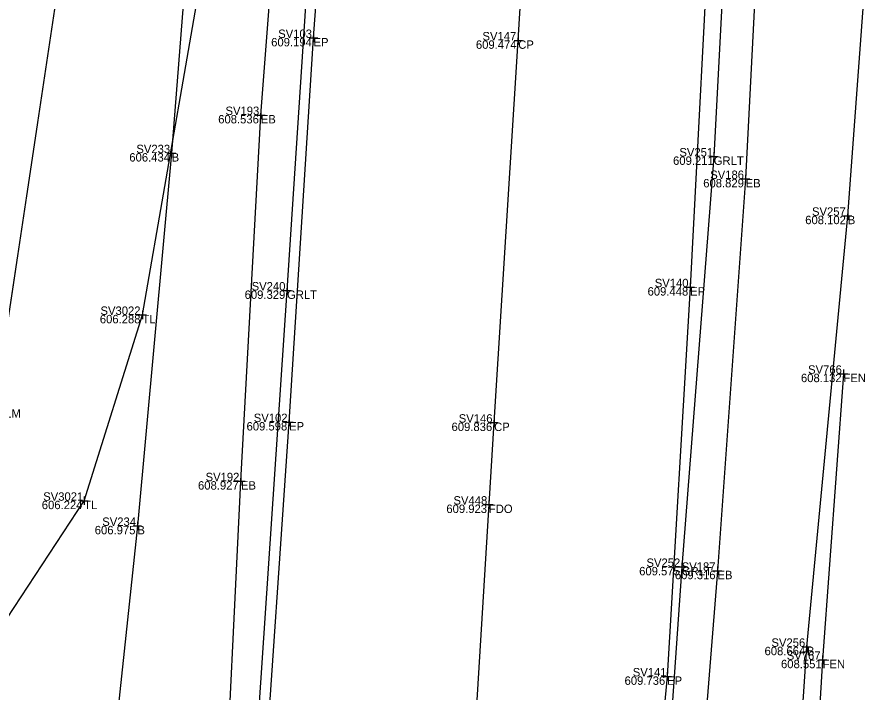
# Model space of a CAD drawing. Extents: x -2 to 1979875, y -2 to 232027.
# Drawn here: x 1978751.3 to 1978801.8, y 231321.8 to 231361.9 of the extents above; entities that cross this region are included whole.
import ezdxf

# ---------------------------------------------------------------- set-up
doc = ezdxf.new("R2010")
doc.units = 0
for name, color, linetype in [('_CIVIL_CONSTRUCTION', 7, 'Continuous'), ('GE_P_Alignment', 7, 'Continuous'), ('GE_P_Alignment_1000_Curve_Data', 7, 'Continuous'), ('GE_P_Alignment_100_Curve_Data', 7, 'Continuous'), ('GE_P_Alignment_500_Curve_Data', 7, 'Continuous'), ('GE_X_Alignment', 7, 'Continuous'), ('GE_X_Alignment_1000_Curve_Data', 7, 'Continuous'), ('GE_X_Alignment_1000_Stations', 7, 'Continuous'), ('GE_X_Alignment_100_Curve_Data', 7, 'Continuous'), ('GE_X_Alignment_100_Stations', 7, 'Continuous'), ('RD_X_Fence', 7, 'Continuous'), ('SC_Scratch1', 7, 'Continuous'), ('UT_X_Water', 7, 'Continuous')]:
    doc.layers.add(name, color=color, linetype=linetype)

msp = doc.modelspace()

# ---------------------------------------------------------------- linework, layer by layer
at = {"layer": 'GE_P_Alignment'}
for points in [[(1978861.689, 231782.415), (1978851.853, 231763.969), (1978841.987, 231745.294), (1978832.802, 231726.204), (1978823.63, 231707.125), (1978815.734, 231686.751), (1978809.08, 231664.461), (1978799.472, 231640.53), (1978791.914, 231616.771), (1978786.956, 231593.117), (1978782.497, 231568.131), (1978778.452, 231542.695), (1978775.331, 231517.531), (1978773.11, 231494.147), (1978771.443, 231473.021), (1978766.839, 231446.726), (1978765.415, 231421.944), (1978763.995, 231399.725), (1978762.317, 231376.717), (1978760.52, 231353.776), (1978758.484, 231331.627), (1978756.746, 231315.247), (1978755.236, 231305.004), (1978757.214, 231296.936)], [(1978796.543, 231298.857), (1978798.274, 231324.443), (1978800.704, 231350.055), (1978802.691, 231376.873), (1978804.911, 231401.653), (1978806.885, 231425.398), (1978807.692, 231450.453), (1978809.926, 231474.524), (1978811.781, 231491.704), (1978814.624, 231521.225), (1978818.445, 231546.214), (1978822.849, 231572.066), (1978827.059, 231594.68), (1978834.582, 231618.811), (1978841.486, 231643.192), (1978848.448, 231666.52), (1978859.661, 231691.186), (1978869.566, 231712.589), (1978880.404, 231735.407), (1978890.398, 231756.483), (1978895.241, 231765.92)]]:
    msp.add_lwpolyline(points, dxfattribs=at)
at = {"layer": 'GE_P_Alignment_1000_Curve_Data'}
msp.add_lwpolyline([(1978733.125, 231254.651), (1978737.318, 231281.706), (1978740.694, 231296.926), (1978742.413, 231306.837), (1978748.228, 231322.336), (1978755.317, 231333.122), (1978758.78, 231344.165), (1978763.011, 231368.433), (1978764.4, 231379.716), (1978765.858, 231395.082), (1978767.238, 231417.341), (1978767.097, 231431.457), (1978767.532, 231441.077), (1978768.449, 231451.786), (1978770.871, 231461.5), (1978774.002, 231474.92), (1978775.889, 231489.026), (1978776.895, 231504.336), (1978777.94, 231514.653)], dxfattribs=at)
at = {"layer": 'GE_P_Alignment_100_Curve_Data'}
for points in [[(1978764.438, 231298.773), (1978765.712, 231320.829), (1978767.378, 231345.616), (1978768.807, 231367.39), (1978770.554, 231391.673), (1978771.722, 231416.416), (1978771.842, 231435.288), (1978771.576, 231449.202)], [(1978801.365, 231447.686), (1978797.734, 231425.84), (1978795.609, 231402.949), (1978794.056, 231378.448), (1978792.74, 231353.579), (1978790.842, 231329.19), (1978789.312, 231307.337), (1978788.697, 231297.789)]]:
    msp.add_lwpolyline(points, dxfattribs=at)
at = {"layer": 'GE_P_Alignment_500_Curve_Data'}
for p, q in [((1978779.373, 231333.143), (1978779.373, 231332.643)), ((1978779.123, 231332.893), (1978779.623, 231332.893)), ((1978779.373, 231332.893), (1978779.373, 231332.893))]:
    msp.add_line(p, q, dxfattribs=at)
at = {"layer": 'GE_X_Alignment_1000_Curve_Data'}
msp.add_lwpolyline([(1978776.88, 231293.019), (1978778.313, 231315.451), (1978779.686, 231337.763), (1978781.119, 231360.475), (1978782.569, 231384.073), (1978784.079, 231408.548), (1978785.737, 231433.04), (1978787.352, 231456.369), (1978789.204, 231480.117), (1978791.477, 231503.648), (1978794.349, 231526.784), (1978797.796, 231550.891), (1978801.515, 231572.898), (1978806.442, 231596.208), (1978812.098, 231619.057), (1978818.629, 231640.775), (1978826, 231662.112), (1978835.057, 231685.412), (1978844.843, 231707.874), (1978854.489, 231728.841), (1978864.575, 231749.812), (1978877.222, 231774.568)], dxfattribs=at)
at = {"layer": 'GE_X_Alignment_1000_Stations'}
for points in [[(1978764.463, 231293.7), (1978765.973, 231315.536), (1978767.501, 231337.797), (1978768.95, 231360.619), (1978770.673, 231383.826), (1978772.372, 231407.034), (1978773.964, 231429.759), (1978775.312, 231448.487), (1978777.194, 231472.049), (1978779.086, 231494.381), (1978781.387, 231516.708), (1978784.451, 231540.773), (1978787.814, 231562.2), (1978793.416, 231590.474), (1978799.132, 231614.141), (1978805.307, 231636.271), (1978811.99, 231656.714), (1978821.006, 231681.034), (1978832.082, 231707.98), (1978843.434, 231732.641), (1978854.786, 231756.844), (1978866.633, 231780.181)], [(1978887.054, 231769.497), (1978875.688, 231747.111), (1978865.322, 231725.635), (1978856.257, 231705.079), (1978847.493, 231684.376), (1978839.463, 231663.377), (1978831.793, 231640.155), (1978824.647, 231616.117), (1978817.773, 231591.521), (1978812.873, 231567.295), (1978809.011, 231544.227), (1978805.416, 231519.882), (1978802.367, 231496.191), (1978799.68, 231465.625), (1978797.956, 231442.353), (1978795.891, 231416.691), (1978793.937, 231391.428), (1978792.627, 231370.424), (1978791.336, 231345.811), (1978789.97, 231322.684), (1978787.965, 231301.579), (1978787.711, 231292.48)]]:
    msp.add_lwpolyline(points, dxfattribs=at)
at = {"layer": 'GE_X_Alignment_100_Curve_Data'}
for p, q in [((1978768.95, 231360.869), (1978768.95, 231360.369)), ((1978781.119, 231360.725), (1978781.119, 231360.225)), ((1978768.7, 231360.619), (1978769.2, 231360.619)), ((1978768.95, 231360.619), (1978768.95, 231360.619)), ((1978780.869, 231360.475), (1978781.369, 231360.475)), ((1978781.119, 231360.475), (1978781.119, 231360.475)), ((1978765.818, 231356.292), (1978765.818, 231355.792)), ((1978765.568, 231356.042), (1978766.068, 231356.042)), ((1978765.818, 231356.042), (1978765.818, 231356.042)), ((1978760.27, 231353.776), (1978760.77, 231353.776)), ((1978760.52, 231354.026), (1978760.52, 231353.526)), ((1978760.52, 231353.776), (1978760.52, 231353.776)), ((1978792.74, 231353.829), (1978792.74, 231353.329)), ((1978792.49, 231353.579), (1978792.99, 231353.579)), ((1978792.74, 231353.579), (1978792.74, 231353.579)), ((1978794.385, 231352.241), (1978794.885, 231352.241)), ((1978794.635, 231352.491), (1978794.635, 231351.991)), ((1978794.635, 231352.241), (1978794.635, 231352.241)), ((1978800.704, 231350.305), (1978800.704, 231349.805)), ((1978800.454, 231350.055), (1978800.954, 231350.055)), ((1978800.704, 231350.055), (1978800.704, 231350.055)), ((1978767.128, 231345.616), (1978767.628, 231345.616)), ((1978767.378, 231345.866), (1978767.378, 231345.366)), ((1978767.378, 231345.616), (1978767.378, 231345.616)), ((1978791.086, 231345.811), (1978791.586, 231345.811)), ((1978791.336, 231346.061), (1978791.336, 231345.561)), ((1978791.336, 231345.811), (1978791.336, 231345.811)), ((1978758.53, 231344.165), (1978759.03, 231344.165)), ((1978758.78, 231344.415), (1978758.78, 231343.915)), ((1978758.78, 231344.165), (1978758.78, 231344.165)), ((1978800.2, 231340.668), (1978800.7, 231340.668)), ((1978800.45, 231340.918), (1978800.45, 231340.418)), ((1978800.45, 231340.668), (1978800.45, 231340.668)), ((1978767.501, 231338.047), (1978767.501, 231337.547)), ((1978779.686, 231338.013), (1978779.686, 231337.513)), ((1978767.251, 231337.797), (1978767.751, 231337.797)), ((1978767.501, 231337.797), (1978767.501, 231337.797)), ((1978779.436, 231337.763), (1978779.936, 231337.763)), ((1978779.686, 231337.763), (1978779.686, 231337.763)), ((1978764.638, 231334.533), (1978764.638, 231334.033)), ((1978764.388, 231334.283), (1978764.888, 231334.283)), ((1978764.638, 231334.283), (1978764.638, 231334.283)), ((1978755.067, 231333.122), (1978755.567, 231333.122)), ((1978755.317, 231333.372), (1978755.317, 231332.872)), ((1978755.317, 231333.122), (1978755.317, 231333.122)), ((1978758.234, 231331.627), (1978758.734, 231331.627)), ((1978758.484, 231331.877), (1978758.484, 231331.377)), ((1978758.484, 231331.627), (1978758.484, 231331.627)), ((1978790.842, 231329.44), (1978790.842, 231328.94)), ((1978790.592, 231329.19), (1978791.092, 231329.19)), ((1978790.842, 231329.19), (1978790.842, 231329.19)), ((1978792.711, 231328.96), (1978793.211, 231328.96)), ((1978792.961, 231329.21), (1978792.961, 231328.71)), ((1978792.961, 231328.96), (1978792.961, 231328.96)), ((1978798.024, 231324.443), (1978798.524, 231324.443)), ((1978798.274, 231324.693), (1978798.274, 231324.193)), ((1978798.274, 231324.443), (1978798.274, 231324.443)), ((1978799.207, 231323.921), (1978799.207, 231323.421)), ((1978798.957, 231323.671), (1978799.457, 231323.671)), ((1978799.207, 231323.671), (1978799.207, 231323.671)), ((1978789.97, 231322.934), (1978789.97, 231322.434)), ((1978789.72, 231322.684), (1978790.22, 231322.684)), ((1978789.97, 231322.684), (1978789.97, 231322.684))]:
    msp.add_line(p, q, dxfattribs=at)
at = {"layer": 'RD_X_Fence'}
msp.add_lwpolyline([(1978800.45, 231340.668), (1978799.207, 231323.671), (1978798.282, 231308.486), (1978798.968, 231301.846)], dxfattribs=at)
at = {"layer": 'SC_Scratch1'}
for points in [[(1978762.241, 231295.643), (1978763.575, 231312.653), (1978764.638, 231334.283), (1978765.818, 231356.042), (1978767.705, 231380.515), (1978769.009, 231402.257), (1978769.844, 231423.935), (1978772.522, 231443.246), (1978774.792, 231466.077), (1978776.974, 231489.898), (1978779.234, 231514.617), (1978782.489, 231539.582), (1978786.101, 231563.808), (1978790.249, 231586.35), (1978795.964, 231611.211), (1978802.838, 231634.974), (1978810.373, 231657.227), (1978818.1, 231678.589), (1978826.474, 231699.286), (1978835.162, 231719.41), (1978844.319, 231739.683), (1978854.914, 231761.571), (1978865.037, 231781.151)], [(1978888.808, 231768.485), (1978877.882, 231747.21), (1978866.825, 231724.389), (1978857.223, 231702.339), (1978848.244, 231681.507), (1978839.526, 231658.205), (1978831.772, 231633.737), (1978825.103, 231611.479), (1978819.562, 231589.918), (1978815.237, 231567.914), (1978810.741, 231543.659), (1978807.235, 231520.012), (1978805.099, 231498.598), (1978802.191, 231475.113), (1978800.521, 231451.185), (1978799.203, 231426.897), (1978797.071, 231402.161), (1978795.912, 231377.319), (1978794.635, 231352.241), (1978792.961, 231328.96), (1978791.062, 231305.225), (1978790.036, 231294.396)]]:
    msp.add_lwpolyline(points, dxfattribs=at)
at = {"layer": 'UT_X_Water'}
msp.add_lwpolyline([(1978712.49, 231209.97), (1978714.812, 231240.893), (1978716.641, 231256.079), (1978724.417, 231285.176), (1978739.059, 231319.254), (1978749.995, 231338.561), (1978758.981, 231398.401), (1978764.286, 231459.71)], dxfattribs=at)

# ---------------------------------------------------------------- texts
at = {"layer": '_CIVIL_CONSTRUCTION'}
for s, p in [('609.194', (1978766.434, 231360.119)), ('609.474', (1978778.603, 231359.975)), ('608.536', (1978763.286, 231355.542)), ('606.434', (1978758.004, 231353.276)), ('609.211', (1978790.322, 231353.079)), ('608.829', (1978792.114, 231351.741)), ('608.102', (1978798.176, 231349.555)), ('609.329', (1978764.857, 231345.116)), ('609.448', (1978788.806, 231345.311)), ('606.288', (1978756.25, 231343.665)), ('608.132', (1978797.922, 231340.168)), ('609.598', (1978764.971, 231337.297)), ('609.836', (1978777.154, 231337.263)), ('608.927', (1978762.087, 231333.783)), ('606.224', (1978752.801, 231332.622)), ('609.923', (1978776.848, 231332.393)), ('606.975', (1978755.949, 231331.127)), ('609.575', (1978788.307, 231328.69)), ('609.316', (1978790.429, 231328.46)), ('608.664', (1978795.758, 231323.943)), ('608.551', (1978796.737, 231323.171)), ('609.736', (1978787.438, 231322.184))]:
    msp.add_text(s, height=0.5, dxfattribs=at).set_placement(p)
at = {"layer": 'GE_X_Alignment'}
for s, p in [('SV103', (1978766.852, 231360.619)), ('SV147', (1978778.994, 231360.475)), ('SV193', (1978763.72, 231356.042)), ('SV233', (1978758.422, 231353.776)), ('SV251', (1978790.697, 231353.579)), ('SV186', (1978792.53, 231352.241)), ('SV257', (1978798.579, 231350.055)), ('SV240', (1978765.274, 231345.616)), ('SV140', (1978789.232, 231345.811)), ('SV3022', (1978756.29, 231344.165)), ('SV766', (1978798.345, 231340.668)), ('SV102', (1978765.4, 231337.797)), ('SV146', (1978777.581, 231337.763)), ('SV192', (1978762.537, 231334.283)), ('SV3021', (1978752.885, 231333.122)), ('SV448', (1978777.27, 231332.893)), ('SV234', (1978756.395, 231331.627)), ('SV252', (1978788.741, 231329.19)), ('SV187', (1978790.836, 231328.96)), ('SV256', (1978796.169, 231324.443)), ('SV767', (1978797.082, 231323.671)), ('SV141', (1978787.927, 231322.684))]:
    msp.add_text(s, height=0.5, dxfattribs=at).set_placement(p)
at = {"layer": 'GE_X_Alignment_100_Stations'}
for s, p in [('EP', (1978768.95, 231360.119)), ('CP', (1978781.119, 231359.975)), ('EB', (1978765.818, 231355.542)), ('B', (1978760.52, 231353.276)), ('GRLT', (1978792.74, 231353.079)), ('EB', (1978794.635, 231351.741)), ('B', (1978800.704, 231349.555)), ('GRLT', (1978767.378, 231345.116)), ('EP', (1978791.336, 231345.311)), ('TL', (1978758.78, 231343.665)), ('FEN', (1978800.45, 231340.168)), ('WLM', (1978749.995, 231338.061)), ('EP', (1978767.501, 231337.297)), ('CP', (1978779.686, 231337.263)), ('EB', (1978764.638, 231333.783)), ('TL', (1978755.317, 231332.622)), ('FDO', (1978779.373, 231332.393)), ('B', (1978758.484, 231331.127)), ('GRLT', (1978790.842, 231328.69)), ('EB', (1978792.961, 231328.46)), ('B', (1978798.274, 231323.943)), ('FEN', (1978799.207, 231323.171)), ('EP', (1978789.97, 231322.184))]:
    msp.add_text(s, height=0.5, dxfattribs=at).set_placement(p)

doc.saveas('drawing.dxf')
